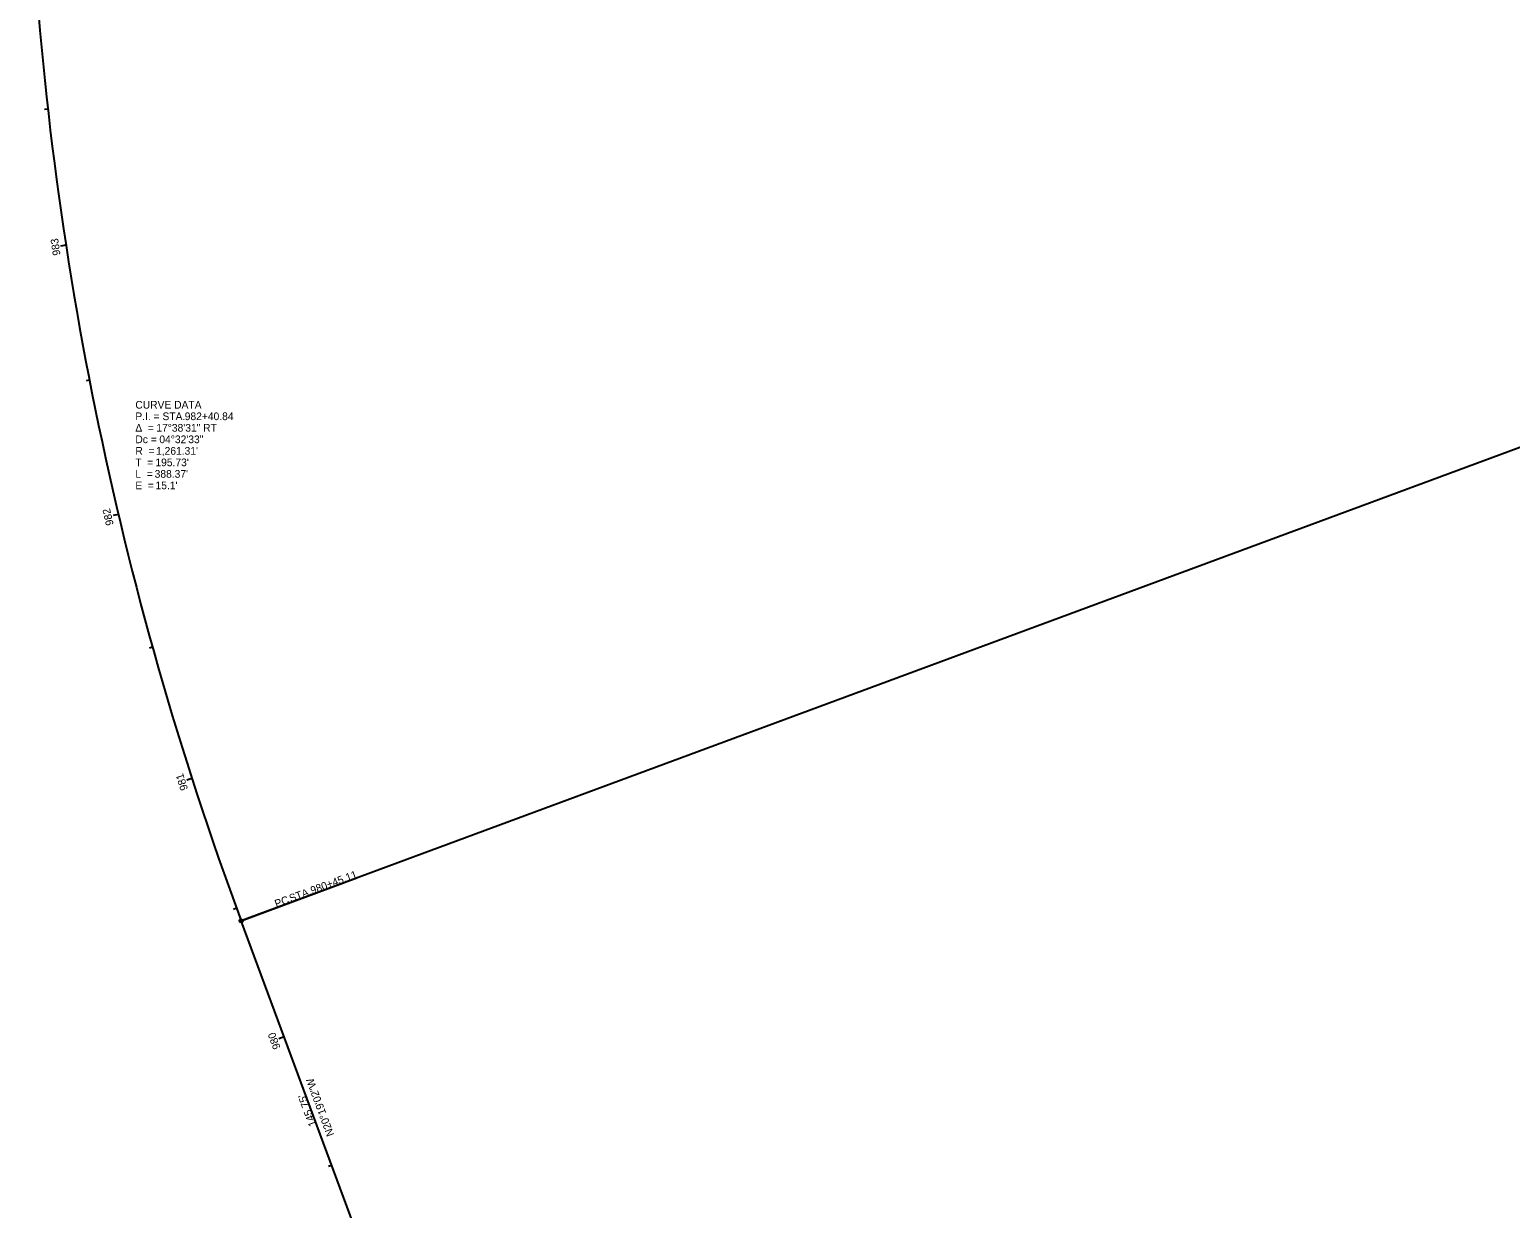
# Model space of a CAD drawing. Extents: x 2227316 to 2230534, y 679272 to 682221.
# Drawn here: x 2228263 to 2228803, y 679701 to 680131 of the extents above; entities that cross this region are included whole.
import ezdxf

# ---------------------------------------------------------------- set-up
doc = ezdxf.new("R2010")
doc.units = 0
for name, color, linetype in [('GE_X_Alignment', 7, 'Continuous'), ('GE_X_Alignment_100_Bearings', 7, 'Continuous'), ('GE_X_Alignment_100_Cardinal_Points', 7, 'Continuous'), ('GE_X_Alignment_100_Curve_Data', 7, 'Continuous'), ('GE_X_Alignment_100_Distances', 7, 'Continuous'), ('GE_X_Alignment_100_Stations', 7, 'Continuous'), ('SC_Scratch1', 7, 'Continuous'), ('SC_Scratch2', 7, 'Continuous')]:
    doc.layers.add(name, color=color, linetype=linetype)

msp = doc.modelspace()

# ---------------------------------------------------------------- linework, layer by layer
at = {"layer": 'GE_X_Alignment'}
msp.add_line((2228390.69, 679669.61), (2228340.08, 679806.29), dxfattribs=at)
msp.add_arc((2229522.92, 680244.24), 1261.31, 182.67534, 200.31734, dxfattribs=at)
at = {"layer": 'GE_X_Alignment_100_Cardinal_Points'}
msp.add_line((2228340.08, 679806.29), (2228382.28, 679821.91), dxfattribs=at)
msp.add_circle((2228340.08, 679806.29), 0.6, dxfattribs=at)
at = {"layer": 'GE_X_Alignment_100_Stations'}
for p, q in [((2228269.64, 680102.17), (2228268.44, 680102.03)), ((2228276.25, 680052.61), (2228274.28, 680052.31)), ((2228284.83, 680003.36), (2228283.65, 680003.13)), ((2228295.35, 679954.48), (2228293.4, 679954.02)), ((2228307.79, 679906.06), (2228306.64, 679905.73)), ((2228322.15, 679858.16), (2228320.25, 679857.55)), ((2228338.39, 679810.88), (2228337.27, 679810.47)), ((2228355.75, 679763.99), (2228353.87, 679763.29)), ((2228373.11, 679717.1), (2228371.98, 679716.68))]:
    msp.add_line(p, q, dxfattribs=at)
at = {"layer": 'SC_Scratch1'}
msp.add_line((2228390.69, 679669.61), (2228340.08, 679806.29), dxfattribs=at)
msp.add_arc((2229522.92, 680244.24), 1261.31, 182.67534, 200.31734, dxfattribs=at)
at = {"layer": 'SC_Scratch2'}
msp.add_line((2229522.92, 680244.24), (2228340.08, 679806.29), dxfattribs=at)

# ---------------------------------------------------------------- texts
at = {"layer": 'GE_X_Alignment_100_Bearings'}
msp.add_text('N20°19\'02"W', height=2.8, rotation=110.3173, dxfattribs=at).set_placement((2228374.07, 679728.33))
at = {"layer": 'GE_X_Alignment_100_Cardinal_Points'}
for s, p in [('980+45.11', (2228365.98, 679815.92)), ('PC', (2228352.93, 679811.08)), (' STA. ', (2228357.24, 679812.68))]:
    msp.add_text(s, height=2.8, rotation=20.3173, dxfattribs=at).set_placement(p)
at = {"layer": 'GE_X_Alignment_100_Curve_Data'}
for s, p in [('CURVE DATA', (2228301.53, 679993.03)), ('Δ  = ', (2228301.53, 679984.63)), ('P.I. = STA. ', (2228301.53, 679988.83)), ('17°38\'31" RT', (2228309.18, 679984.63)), ('982+40.84', (2228319.53, 679988.83)), ('Dc = ', (2228301.53, 679980.43)), ('04°32\'33"', (2228310.28, 679980.43)), ('R  = ', (2228301.53, 679976.23)), ("1,261.31'", (2228309.07, 679976.23)), ('T  = ', (2228301.53, 679972.03)), ('L  = ', (2228301.53, 679967.83)), ("388.37'", (2228308.57, 679967.83)), ("195.73'", (2228308.85, 679972.03)), ('E  = ', (2228301.53, 679963.63)), ("15.1'", (2228308.88, 679963.63))]:
    msp.add_text(s, height=2.8, dxfattribs=at).set_placement(p)
at = {"layer": 'GE_X_Alignment_100_Distances'}
msp.add_text("145.75'", height=2.8, rotation=110.3173, dxfattribs=at).set_placement((2228367.59, 679731.9))
at = {"layer": 'GE_X_Alignment_100_Stations'}
for s, rotation, p in [('983', 98.7386, (2228274.27, 680049.07)), ('982', 103.2812, (2228293.65, 679950.78)), ('981', 107.8237, (2228320.76, 679854.33)), ('980', 110.3173, (2228354.54, 679760.05))]:
    msp.add_text(s, height=2.8, rotation=rotation, dxfattribs=at).set_placement(p)

doc.saveas('drawing.dxf')
